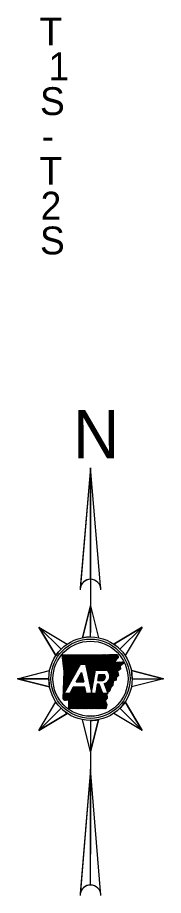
# Model space of a CAD drawing. Extents: x -712 to 3943, y 73 to 2823.
# Drawn here: x 2497 to 2602, y 763 to 1394 of the extents above; entities that cross this region are included whole.
import ezdxf

# ---------------------------------------------------------------- set-up
doc = ezdxf.new("R2010")
doc.units = 0
doc.layers.add('Default', color=7, linetype='Continuous')
doc.layers.add('R_Draft', color=7, linetype='Continuous')

msp = doc.modelspace()

# ---------------------------------------------------------------- linework, layer by layer
at = {"layer": 'R_Draft'}
for p, q in [((2549.78, 1070.31), (2542.39, 983.83)), ((2549.78, 1070.31), (2549.78, 951.88)), ((2549.78, 990.06), (2549.78, 1070.31)), ((2542.49, 985.04), (2542.83, 985.38)), ((2542.53, 985.5), (2543.22, 986.19)), ((2549.78, 971.1), (2543.94, 948.03)), ((2549.78, 948.6), (2549.78, 971.1)), ((2512.66, 955.72), (2528.57, 939.81)), ((2528.57, 939.81), (2512.66, 955.72)), ((2512.66, 955.72), (2524.84, 935.28)), ((2586.91, 955.72), (2566.46, 943.54)), ((2571, 939.81), (2586.91, 955.72)), ((2571, 939.81), (2586.91, 955.72)), ((2529.33, 935.51), (2529.6, 935.77)), ((2529.43, 934.75), (2530.45, 935.77)), ((2529.52, 934), (2531.29, 935.77)), ((2529.62, 933.25), (2532.14, 935.77)), ((2529.71, 932.49), (2532.99, 935.77)), ((2529.8, 931.74), (2533.84, 935.77)), ((2529.9, 930.98), (2534.69, 935.77)), ((2529.99, 930.23), (2535.53, 935.77)), ((2530.09, 929.47), (2536.38, 935.77)), ((2530.18, 928.72), (2537.23, 935.77)), ((2530.27, 927.96), (2538.08, 935.77)), ((2530.37, 927.21), (2538.93, 935.77)), ((2530.46, 926.45), (2539.77, 935.77)), ((2530.56, 925.7), (2540.62, 935.77)), ((2530.58, 917.24), (2549.12, 935.78)), ((2530.61, 918.12), (2548.27, 935.78)), ((2530.64, 919), (2547.42, 935.78)), ((2530.65, 924.95), (2541.47, 935.77)), ((2530.67, 919.88), (2546.57, 935.78)), ((2530.7, 920.75), (2545.72, 935.78)), ((2530.73, 921.63), (2544.87, 935.78)), ((2530.74, 924.19), (2542.32, 935.77)), ((2530.76, 922.51), (2544.02, 935.77)), ((2530.79, 923.39), (2543.17, 935.77)), ((2543.18, 929), (2549.97, 935.79)), ((2544.03, 929), (2550.82, 935.79)), ((2544.88, 929), (2551.68, 935.79)), ((2545.73, 929), (2552.54, 935.81)), ((2546.26, 928.68), (2553.4, 935.82)), ((2546.41, 927.98), (2554.27, 935.83)), ((2546.56, 927.28), (2555.13, 935.85)), ((2546.71, 926.58), (2555.99, 935.86)), ((2546.86, 925.88), (2556.85, 935.88)), ((2547.01, 925.18), (2557.71, 935.89)), ((2547.16, 924.48), (2558.58, 935.9)), ((2547.31, 923.78), (2559.44, 935.92)), ((2547.45, 923.08), (2560.3, 935.93)), ((2547.6, 922.38), (2561.16, 935.94)), ((2547.75, 921.69), (2562.02, 935.96)), ((2547.9, 920.99), (2562.89, 935.97)), ((2548.05, 920.29), (2563.75, 935.98)), ((2548.2, 919.59), (2564.62, 936.01)), ((2554.1, 924.63), (2565.49, 936.03)), ((2554.95, 924.63), (2566.36, 936.05)), ((2555.79, 924.63), (2567.22, 936.07)), ((2556.64, 924.63), (2568.09, 936.09)), ((2557.49, 924.63), (2568.96, 936.11)), ((2558.34, 924.63), (2569.15, 935.45)), ((2559.19, 924.63), (2569.56, 935.01)), ((2560.04, 924.63), (2569.67, 934.27)), ((2530.55, 916.37), (2542, 927.82)), ((2530.84, 908.09), (2542.67, 929)), ((2542.67, 929), (2546.19, 929)), ((2560.89, 924.63), (2567.73, 931.48)), ((2561.66, 924.56), (2567.57, 930.47)), ((2562.12, 924.17), (2568.46, 930.51)), ((2562.53, 923.74), (2569.36, 930.56)), ((2562.9, 923.26), (2570.25, 930.61)), ((2563.22, 922.72), (2571.14, 930.65)), ((2563.47, 922.13), (2572.04, 930.7)), ((2563.67, 921.48), (2572.84, 930.65)), ((2563.78, 920.75), (2573.24, 930.2)), ((2572.86, 928.98), (2573.64, 929.75)), ((2530.47, 913.73), (2538.68, 921.95)), ((2530.5, 914.61), (2539.79, 923.9)), ((2530.53, 915.49), (2540.9, 925.86)), ((2539.54, 916.3), (2543.41, 923.13)), ((2540.6, 918.16), (2543.79, 921.36)), ((2541.7, 920.11), (2543.65, 922.05)), ((2542.81, 922.07), (2543.5, 922.75)), ((2548.35, 918.89), (2553.17, 923.7)), ((2548.5, 918.19), (2552.99, 922.68)), ((2548.65, 917.49), (2552.81, 921.65)), ((2553.33, 924.63), (2561.55, 924.63)), ((2555.12, 917.22), (2559.58, 921.68)), ((2555.29, 918.24), (2558.73, 921.68)), ((2555.47, 919.27), (2557.89, 921.68)), ((2555.65, 920.3), (2557.04, 921.68)), ((2555.83, 921.32), (2556.19, 921.68)), ((2555.89, 921.68), (2559.75, 921.68)), ((2560.11, 913.68), (2569.52, 923.08)), ((2560.34, 913.06), (2569.67, 922.39)), ((2560.57, 912.44), (2569.83, 921.7)), ((2562.87, 917.29), (2569.36, 923.77)), ((2563.61, 918.88), (2571.31, 926.58)), ((2563.79, 919.9), (2571.22, 927.33)), ((2570.36, 924.78), (2571.41, 925.83)), ((2602.28, 918.6), (2579.21, 924.44)), ((2497.28, 918.6), (2519.78, 918.6)), ((2519.78, 918.6), (2497.28, 918.6)), ((2497.28, 918.6), (2520.36, 912.76)), ((2530.38, 911.1), (2535.36, 916.08)), ((2530.41, 911.98), (2536.47, 918.03)), ((2530.44, 912.85), (2537.57, 919.99)), ((2539.54, 916.3), (2544.88, 916.3)), ((2539.58, 916.3), (2543.94, 920.66)), ((2540.43, 916.3), (2544.09, 919.96)), ((2541.28, 916.3), (2544.24, 919.26)), ((2542.13, 916.3), (2544.39, 918.56)), ((2542.98, 916.3), (2544.54, 917.86)), ((2543.83, 916.3), (2544.69, 917.16)), ((2544.68, 916.3), (2544.84, 916.46)), ((2548.8, 916.79), (2552.63, 920.62)), ((2548.95, 916.09), (2552.45, 919.59)), ((2549.1, 915.4), (2552.27, 918.57)), ((2549.25, 914.7), (2552.09, 917.54)), ((2549.4, 914), (2551.91, 916.51)), ((2549.55, 913.3), (2551.73, 915.48)), ((2555.11, 917.22), (2558.64, 917.22)), ((2555.97, 917.22), (2560.05, 921.31)), ((2556.82, 917.22), (2560.34, 920.75)), ((2557.66, 917.22), (2560.5, 920.05)), ((2558.51, 917.22), (2560.43, 919.13)), ((2559.58, 915.09), (2562.17, 908.09)), ((2559.65, 914.92), (2559.91, 915.17)), ((2559.88, 914.3), (2561.5, 915.91)), ((2560.8, 911.82), (2569.99, 921.01)), ((2561.02, 911.2), (2566.11, 916.29)), ((2561.25, 910.58), (2566.02, 915.34)), ((2567.09, 917.26), (2568.28, 918.45)), ((2579.78, 918.6), (2602.28, 918.6)), ((2579.78, 918.6), (2602.28, 918.6)), ((2530.29, 908.47), (2532.03, 910.21)), ((2530.32, 909.34), (2533.14, 912.17)), ((2530.35, 910.22), (2534.25, 914.12)), ((2530.48, 903.56), (2539.39, 912.48)), ((2530.98, 903.22), (2540.24, 912.48)), ((2531.59, 902.98), (2541.09, 912.48)), ((2532.6, 903.14), (2541.94, 912.48)), ((2533.46, 903.15), (2542.79, 912.48)), ((2534.12, 902.97), (2543.64, 912.48)), ((2534.15, 902.15), (2544.49, 912.48)), ((2534.16, 901.3), (2545.33, 912.48)), ((2534.16, 900.45), (2545.78, 912.08)), ((2534.16, 899.61), (2545.93, 911.38)), ((2534.16, 898.76), (2546.08, 910.68)), ((2534.16, 897.91), (2546.23, 909.98)), ((2534.18, 897.08), (2546.38, 909.28)), ((2537.38, 912.48), (2534.9, 908.09)), ((2535.86, 909.79), (2538.55, 912.48)), ((2536.97, 911.75), (2537.7, 912.48)), ((2545.69, 912.48), (2537.38, 912.48)), ((2542.65, 897.06), (2557.24, 911.66)), ((2543.5, 897.06), (2557.47, 911.04)), ((2544.34, 897.06), (2557.7, 910.42)), ((2545.19, 897.06), (2557.93, 909.8)), ((2546.04, 897.06), (2558.16, 909.18)), ((2549.7, 912.6), (2551.56, 914.46)), ((2549.85, 911.9), (2551.38, 913.43)), ((2550, 911.2), (2551.2, 912.4)), ((2550.15, 910.5), (2551.02, 911.37)), ((2550.3, 909.8), (2550.84, 910.35)), ((2550.45, 909.1), (2550.66, 909.32)), ((2553.67, 908.93), (2557.01, 912.28)), ((2553.85, 909.96), (2556.79, 912.9)), ((2554.03, 910.99), (2556.56, 913.52)), ((2554.21, 912.02), (2556.33, 914.14)), ((2554.39, 913.04), (2556.08, 914.74)), ((2554.56, 914.07), (2555.23, 914.74)), ((2556.11, 914.74), (2554.68, 914.74)), ((2558.56, 908.09), (2556.11, 914.74)), ((2561.48, 909.96), (2565.92, 914.4)), ((2561.71, 909.34), (2564.31, 911.94)), ((2561.94, 908.72), (2563.95, 910.73)), ((2530.16, 904.09), (2534.16, 908.09)), ((2530.18, 904.96), (2533.31, 908.09)), ((2530.2, 905.83), (2532.46, 908.09)), ((2530.23, 906.71), (2531.61, 908.09)), ((2530.26, 907.59), (2530.93, 908.25)), ((2534.9, 908.09), (2530.84, 908.09)), ((2535.02, 897.08), (2546.53, 908.58)), ((2535.87, 897.08), (2546.89, 908.09)), ((2536.72, 897.07), (2547.74, 908.09)), ((2537.57, 897.07), (2548.58, 908.09)), ((2538.41, 897.07), (2549.43, 908.09)), ((2539.26, 897.07), (2550.28, 908.09)), ((2540.11, 897.07), (2551.13, 908.09)), ((2540.95, 897.07), (2551.98, 908.09)), ((2541.8, 897.07), (2552.83, 908.09)), ((2553.52, 908.09), (2546.63, 908.09)), ((2546.88, 897.06), (2558.39, 908.56)), ((2547.73, 897.06), (2558.77, 908.09)), ((2548.58, 897.06), (2559.62, 908.09)), ((2549.43, 897.05), (2560.46, 908.09)), ((2550.27, 897.05), (2561.31, 908.09)), ((2551.12, 897.05), (2561.6, 907.53)), ((2551.97, 897.05), (2561.63, 906.72)), ((2552.81, 897.05), (2561.67, 905.91)), ((2553.66, 897.05), (2561.71, 905.1)), ((2554.51, 897.05), (2560.32, 902.85)), ((2562.17, 908.09), (2558.56, 908.09)), ((2512.66, 881.48), (2528.57, 897.39)), ((2528.57, 897.39), (2512.66, 881.48)), ((2555.36, 897.04), (2560.58, 902.27)), ((2556.2, 897.04), (2560.84, 901.68)), ((2557.05, 897.04), (2561.1, 901.09)), ((2557.9, 897.04), (2561.36, 900.51)), ((2558.74, 897.04), (2561.58, 899.88)), ((2559.59, 897.04), (2561.2, 898.64)), ((2560.44, 897.04), (2560.82, 897.41)), ((2571, 897.39), (2586.91, 881.48)), ((2571, 897.39), (2586.91, 881.48)), ((2586.91, 881.48), (2574.72, 901.92)), ((2512.66, 881.48), (2533.11, 893.66)), ((2549.78, 866.1), (2555.62, 889.17)), ((2549.78, 888.6), (2549.78, 888.6)), ((2549.78, 888.6), (2549.78, 792.56)), ((2549.78, 888.6), (2549.78, 866.1)), ((2549.78, 853.56), (2542.38, 764.04)), ((2549.78, 770.31), (2549.78, 853.56))]:
    msp.add_line(p, q, dxfattribs=at)
for points in [[(2557.28, 982.56), (2549.78, 1070.31), (2542.28, 982.56)], [(2543.94, 948.03), (2549.78, 971.1), (2555.62, 948.03)], [(2524.84, 935.28), (2512.66, 955.72), (2533.11, 943.54)], [(2566.46, 943.54), (2586.91, 955.72), (2574.72, 935.28)], [(2529.3, 935.77), (2541.01, 935.77), (2551.28, 935.79), (2563.4, 935.98), (2569.02, 936.11)], [(2530.15, 904.1), (2530.8, 923.74), (2529.3, 935.77)], [(2546.19, 929), (2550.54, 908.65), (2553.33, 924.63)], [(2572.69, 930.73), (2573.71, 929.67), (2571.18, 927.59), (2571.45, 925.5), (2569.29, 924.07), (2570.03, 920.85), (2568.36, 919.32), (2568.21, 917.67), (2566.18, 916.94), (2565.86, 913.81), (2564.41, 912.25), (2563.7, 909.9), (2561.58, 907.95), (2561.74, 904.52), (2560.29, 902.9), (2561.61, 899.96), (2560.7, 897.04)], [(2567.28, 930.45), (2572.77, 930.74)], [(2520.36, 912.76), (2497.28, 918.6), (2520.36, 924.44)], [(2543.41, 923.13), (2544.88, 916.3)], [(2555.11, 917.22), (2555.89, 921.68)], [(2579.21, 924.44), (2602.28, 918.6), (2579.21, 912.76)], [(2546.63, 908.09), (2545.69, 912.48)], [(2554.68, 914.74), (2553.52, 908.09)], [(2560.7, 897.04), (2534.17, 897.08), (2534.15, 902.94)], [(2533.11, 893.66), (2512.66, 881.48), (2524.84, 901.92)], [(2574.72, 901.92), (2586.91, 881.48), (2566.46, 893.66)], [(2555.62, 889.17), (2549.78, 866.1), (2543.94, 889.17)], [(2557.28, 762.81), (2549.78, 853.56), (2542.28, 762.81)]]:
    msp.add_lwpolyline(points, dxfattribs=at)
for radius in [30, 28.5, 27]:
    msp.add_circle((2549.78, 918.6), radius, dxfattribs=at)
for centre, radius, start, end in [((2549.78, 982.56), 7.5, 0, 180), ((2549.78, 982.56), 7.5, 90, 170.22959), ((2549.78, 918.6), 30, 90, 101.22909), ((2549.78, 918.6), 30, 45, 56.22909), ((2549.78, 918.6), 30, 135, 146.22909), ((2557.79, 919.8), 2.72, 288.12683, 43.89016), ((2558.49, 920.29), 5.31, 281.86262, 54.87052), ((2549.78, 918.6), 30, 0, 11.22909), ((2549.78, 918.6), 30, 180, 191.22909), ((2549.78, 918.6), 30, 225, 236.22909), ((2549.78, 918.6), 30, 315, 326.22909), ((2549.78, 918.6), 30, 270, 281.22909), ((2549.78, 762.81), 7.5, 0, 180), ((2549.78, 762.81), 7.5, 90, 170.5511)]:
    msp.add_arc(centre, radius, start, end, dxfattribs=at)
for points in [[(2569.02, 936.11), (2569.05, 935.79), (2569.15, 935.62), (2569.17, 935.32), (2569.29, 935.19), (2569.5, 935.06), (2569.69, 934.85), (2569.73, 934.6), (2569.68, 934.35), (2569.66, 934.07), (2569.63, 933.82), (2569.59, 933.59), (2569.41, 933.41), (2569.25, 933.28), (2569.1, 933.13), (2568.99, 932.97), (2568.8, 932.8), (2568.61, 932.62), (2568.46, 932.46), (2568.31, 932.26), (2568.23, 932.03), (2568.07, 931.87), (2567.94, 931.73), (2567.76, 931.53), (2567.68, 931.34), (2567.51, 931.11), (2567.47, 930.89), (2567.37, 930.72), (2567.36, 930.69)], [(2534.15, 902.94), (2534.18, 902.92), (2534.04, 903.02), (2533.85, 903.11), (2533.64, 903.12), (2533.38, 903.16), (2533.15, 903.18), (2532.92, 903.33), (2532.67, 903.17), (2532.4, 903.06), (2532.24, 903.19), (2532.03, 903.1), (2531.88, 903.15), (2531.63, 902.97), (2531.39, 903.04), (2531.22, 902.99), (2531, 902.99), (2530.96, 903.24), (2530.75, 903.28), (2530.57, 903.38), (2530.44, 903.63), (2530.36, 903.83), (2530.15, 904.1)]]:
    msp.add_spline(points, degree=3, dxfattribs=at)

# ---------------------------------------------------------------- texts
at = {"layer": 'Default'}
for s, p in [('T', (2513.04, 1373.87)), ('1', (2519.58, 1348.84)), ('S', (2513.44, 1323.8)), ('-', (2514.69, 1298.76)), ('T', (2513.04, 1273.72)), ('2', (2513.91, 1248.68)), ('S', (2513.44, 1223.64))]:
    msp.add_text(s, height=20, dxfattribs=at).set_placement(p)
at = {"layer": 'R_Draft'}
for s, height, p in [('N', 34.62, (2537.13, 1077.12)), ('DWB 7-27-17', 0.5833, (2547.95, 891.1))]:
    msp.add_text(s, height=height, dxfattribs=at).set_placement(p)

doc.saveas('drawing.dxf')
